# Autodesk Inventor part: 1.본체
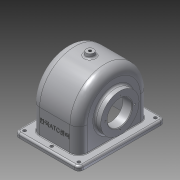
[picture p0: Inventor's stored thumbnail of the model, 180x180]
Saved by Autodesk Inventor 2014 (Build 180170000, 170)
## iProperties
Created: 2015-09
Part Number: 1.본체
Material: 알루미늄 6061
Document SubType Name: Modeling
Designer: Owner
Density: 2.71 g/cm^3
Appearance: 알루미늄 - 평지
Mass: 724.907 g
Surface Area: 899.144 cm^2
Volume: 267.493 cm^3
Author: Owner
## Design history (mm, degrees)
sketch "스케치9"
  geometry: L1 (-38.5, 57)-(38.5, 57); L2 (38.5, 57)-(38.5, -57); L3 (38.5, -57)-(-38.5, -57); L4 (-38.5, -57)-(-38.5, 57); L5 (-38.5, 57)-(38.5, -57); L6 (38.5, 57)-(-38.5, -57); 1 further point
  constraints: 12 end point, 2 midpoint, 2 parallel, 1 horizontal, 1 perpendicular
  dimensions: "d54" = 114 distance of L1.end L2.end; "d55" = 77 distance of L1.start L1.end
extrude "돌출6" new body sketch "스케치9" distance "d56" = 104; taper "d57" = 0 deg
fillet "모깎기5" dims "d58" = 57
feature "쉘3" dims "d60" = 6
node "작업 평면1"
sketch "스케치10"
  geometry: L1 (0, 108)-(-47, 108) reference; L2 (0, 6)-(0, 108) reference; L3 (0, 6)-(-47, 6) reference; L4 (-47, 6)-(0, 6); L5 (0, 108)-(-47, 108); L6 (0, 108)-(0, 6); A1 r 51 centre (-47, 57) between (-47, 108) and (-47, 6) reference; A2 r 51 centre (-47, 57) between (-47, 108) and (-47, 6); 1 further point
  constraints: 6 end point, 3 collinear, 3 point on circle, 2 tangent, 1 centre point, 1 coincident, 1 concentric, 1 point on line
extrude "돌출7" cut sketch "스케치10" distance "d62" = 67; taper "d63" = 0 deg
sketch "스케치11"
  geometry: L1 (38.5, 57)-(-38.5, 57) reference; L2 (-38.5, 57)-(-38.5, -57) reference; L3 (-38.5, -57)-(38.5, -57) reference; L4 (38.5, -57)-(38.5, 57) reference; L5 (-52, 70)-(52, 70); L6 (52, 70)-(52, -70); L7 (52, -70)-(-52, -70); L8 (-52, -70)-(-52, 70); L9 (-52, 70)-(52, -70); L10 (52, 70)-(-52, -70); 1 further point
  constraints: 12 end point, 2 midpoint, 2 parallel, 1 horizontal, 1 perpendicular
  dimensions: "d64" = 140 distance of L5.end L6.end; "d65" = 104 distance of L5.start L5.end
extrude "돌출8" join sketch "스케치11" distance "d66" = 7; taper "d67" = 0 deg
sketch "스케치12"
  geometry: C1 r 31 at (0, 0); A1 r 57 centre (0, 0) between (0, 57) and (0, -57) reference; 1 further point
  constraints: 1 centre point, 1 coincident
  dimensions: "d68" = 62 diameter of C1
extrude "돌출9" join sketch "스케치12" distance "d69" = 10; taper "d70" = 0 deg
sketch "스케치13"
  geometry: L1 (74.597, 47)-(-83.393, 47); L2 (-33.5, 0)-(33.5, 0) reference; L3 (38.5, 104)-(38.5, 47) reference; L4 (38.5, 90.943)-(19.5, 75); L5 (19.5, 75)-(19.5, 47); L6 (38.5, 84.416)-(38.5, 90.943); L7 (19.5, 47)-(38.5, 47); L8 (38.5, 84.416)-(33.237, 80); L9 (33.237, 80)-(35.5, 80); L10 (35.5, 80)-(35.5, 67); L11 (35.5, 67)-(19.5, 67); 1 further point
  constraints: 18 end point, 3 parallel, 3 perpendicular, 3 point on line, 1 horizontal
  dimensions: "d71" = 47 distance between parallel lines of L1 L2; "d72" = 56 diameter of L4.end L1; "d73" = 50 deg angle of L4 L5; "d74" = 19 distance between parallel lines of L3 L5; "d76" = 16 distance of L10.end L11.end; "d77" = 40 diameter of L11 L1; "d78" = 66 diameter of L9.end L1; "d79" = 5 distance between parallel lines of L4 L8
revolve "회전3" stored, may be unused: angle "d75" = 90 deg
revolve "회전4" stored, may be unused: angle "d80" = 90 deg
hole "구멍3" diameter "d83" = 40; stored, may be unused: countersink angle "d87" = 90 deg, drill point angle "d89" = 118 deg; dims "d81" = 10, "d82" = 10, "d84" = 6, "d85" = 4, "d86" = 2, "d88" = 8
sketch "스케치14"
  geometry: C1 r 33 at (0, 0) reference; 2 further points
  constraints: 1 horizontal alignment
  dimensions: "d90" = 28 distance of C1.centre point (28, 0)
hole "구멍4" sketch "스케치14" at (28, 0) diameter "d91" = 2.459; stored, may be unused: countersink angle "d95" = 90 deg, drill point angle "d97" = 118 deg; dims "d92" = 7, "d93" = 4, "d94" = 2, "d96" = 9
sketch "스케치15"
  geometry: C1 r 20 at (0, 0) reference; 2 further points
  constraints: 1 horizontal alignment
  dimensions: "d101" = 24 distance of point (-24, 0) C1.centre
hole "구멍5" sketch "스케치15" at (-24, 0) diameter "d102" = 2.459; stored, may be unused: countersink angle "d106" = 90 deg, drill point angle "d108" = 118 deg; dims "d103" = 6, "d104" = 4, "d105" = 2, "d107" = 8
hole "구멍6" diameter "d114" = 5; stored, may be unused: countersink angle "d118" = 90 deg, drill point angle "d120" = 118 deg; dims "d112" = 8, "d113" = 8, "d115" = 6, "d116" = 4, "d117" = 2, "d119" = 8
node "작업 평면2"
sketch "스케치17"
  geometry: C1 r 6 at (0, 0); 1 further point
  constraints: 1 centre point, 1 coincident
  dimensions: "d128" = 12 diameter of C1
extrude "돌출10" join sketch "스케치17" distance "d129" = 10; taper "d130" = 10 deg
hole "구멍7" diameter "d133" = 4.459; stored, may be unused: countersink angle "d137" = 90 deg, drill point angle "d139" = 118 deg; dims "d131" = 10, "d132" = 10, "d134" = 6, "d135" = 4, "d136" = 2, "d138" = 8
fillet "모깎기6" dims "d140" = 14, "d141" = 9
fillet "모깎기7" dims "d142" = 1, "d143" = 7, "d144" = 0.5
chamfer "모따기1" distance "d145" = 1; stored, may be unused: second distance "d146" = 2, angle "d147" = 45 deg
fillet "모깎기8" dims "d148" = 3
sketch "스케치19"
  geometry: L1 (-20.5, -47)-(69.5, -47) reference; L2 (-14, 0)-(-14, -39) reference; 2 further points
  constraints: 1 other
  dimensions: "d149" = 30 distance from line of point (24.5, -17) L1; "d150" = 38.5 distance from line of point (24.5, -17) L2
feature "엠보싱1" sketch "스케치19" dims "d54" = 114, "d55" = 77, "d151" = 0.5, "d152" = 0
node "솔리드2"
pattern_circular "원형 패턴1" dims angle "d99" = 360 deg
pattern_circular "원형 패턴2" dims angle "d110" = 360 deg
pattern_linear "직사각형 패턴1" dims "d123" = 44, "d126" = 124
node "투영된 루프1"
other parameters: "d61" = -5
